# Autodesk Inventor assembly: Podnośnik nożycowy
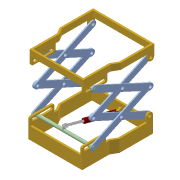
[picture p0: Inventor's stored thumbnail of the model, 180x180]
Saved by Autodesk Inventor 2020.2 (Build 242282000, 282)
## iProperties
Manager: www.cadconsulting.pl
Company: Fabian Stasiak CAD Consulting
Created: 2006-06
Part Number: Podnośnik nożycowy
Document SubType Name: Assembly
Designer: F.Stasiak
Author: F.Stasiak
Subject: Zbiór ćwiczeń. Autodesk Inventor 2020. Kurs podstawowy
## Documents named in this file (7)
- C:\2020_Kurs_podstawowy\R6 Zespoły\Adaptacyjność\Podnośnik nożycowy.iam
- C:\2020_Kurs_podstawowy\R6 Zespoły\Adaptacyjność\Podstawa_A100.ipt
- C:\2020_Kurs_podstawowy\R6 Zespoły\Adaptacyjność\Nożyce_A100.iam
- C:\2020_Kurs_podstawowy\R6 Zespoły\Adaptacyjność\Pręt_A100.ipt
- C:\2020_Kurs_podstawowy\R6 Zespoły\Adaptacyjność\Kosz_A100.ipt
- C:\2020_Kurs_podstawowy\R6 Zespoły\Adaptacyjność\Pręt2_A100.ipt
- C:\2020_Kurs_podstawowy\R6 Zespoły\Adaptacyjność\Siłownik_401.iam
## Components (7 placed, 6 different names)
1. Podstawa_A100:1 — Wstaw:1, Zestawiający:3, Wstaw:2, Wstaw:4, Równoległy:4
2. Nożyce_A100:1 [sub-assembly] — Wstaw:1, Zestawiający:1, Równoległy:1, Zestawiający:6, Równoległy:3
3. Nożyce_A100:2 [sub-assembly] — Zestawiający:2, Równoległy:2, Wstaw:2, Wstaw:3
4. Siłownik_401:1 [sub-assembly] — Wstaw:4, Zestawiający:8, Kąt:1
5. Pręt_A100:1 — Zestawiający:1, Zestawiający:2, Równoległy:1, Równoległy:2, Zestawiający:3, Zestawiający:8, Kąt:1
6. Kosz_A100:1 — Wstaw:3, Zestawiający:7, Równoległy:4
7. Pręt2_A100:1 — Zestawiający:6, Równoległy:3, Zestawiający:7
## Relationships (15: Mate 6, Insert 4, Flush 4, Angle 1)
- Wstaw:1 [Insert]: Podstawa_A100:1 ↔ Nożyce_A100:1
- Zestawiający:1 [Mate]: Nożyce_A100:1 ↔ Pręt_A100:1
- Zestawiający:2 [Mate]: Nożyce_A100:2 ↔ Pręt_A100:1
- Równoległy:1 [Flush]: Nożyce_A100:1 ↔ Pręt_A100:1
- Równoległy:2 [Flush]: Nożyce_A100:2 ↔ Pręt_A100:1
- Zestawiający:3 [Mate]: Podstawa_A100:1 ↔ Pręt_A100:1
- Wstaw:2 [Insert]: Podstawa_A100:1 ↔ Nożyce_A100:2
- Wstaw:3 [Insert]: Nożyce_A100:2 ↔ Kosz_A100:1
- Zestawiający:6 [Mate]: Nożyce_A100:1 ↔ Pręt2_A100:1
- Równoległy:3 [Flush]: Nożyce_A100:1 ↔ Pręt2_A100:1
- Zestawiający:7 [Mate]: Kosz_A100:1 ↔ Pręt2_A100:1
- Wstaw:4 [Insert]: Podstawa_A100:1 ↔ Siłownik_401:1
- Zestawiający:8 [Mate]: Siłownik_401:1 ↔ Pręt_A100:1
- Równoległy:4 [Flush]: Podstawa_A100:1 ↔ Kosz_A100:1
- Kąt:1 [Angle]: Siłownik_401:1 ↔ Pręt_A100:1
